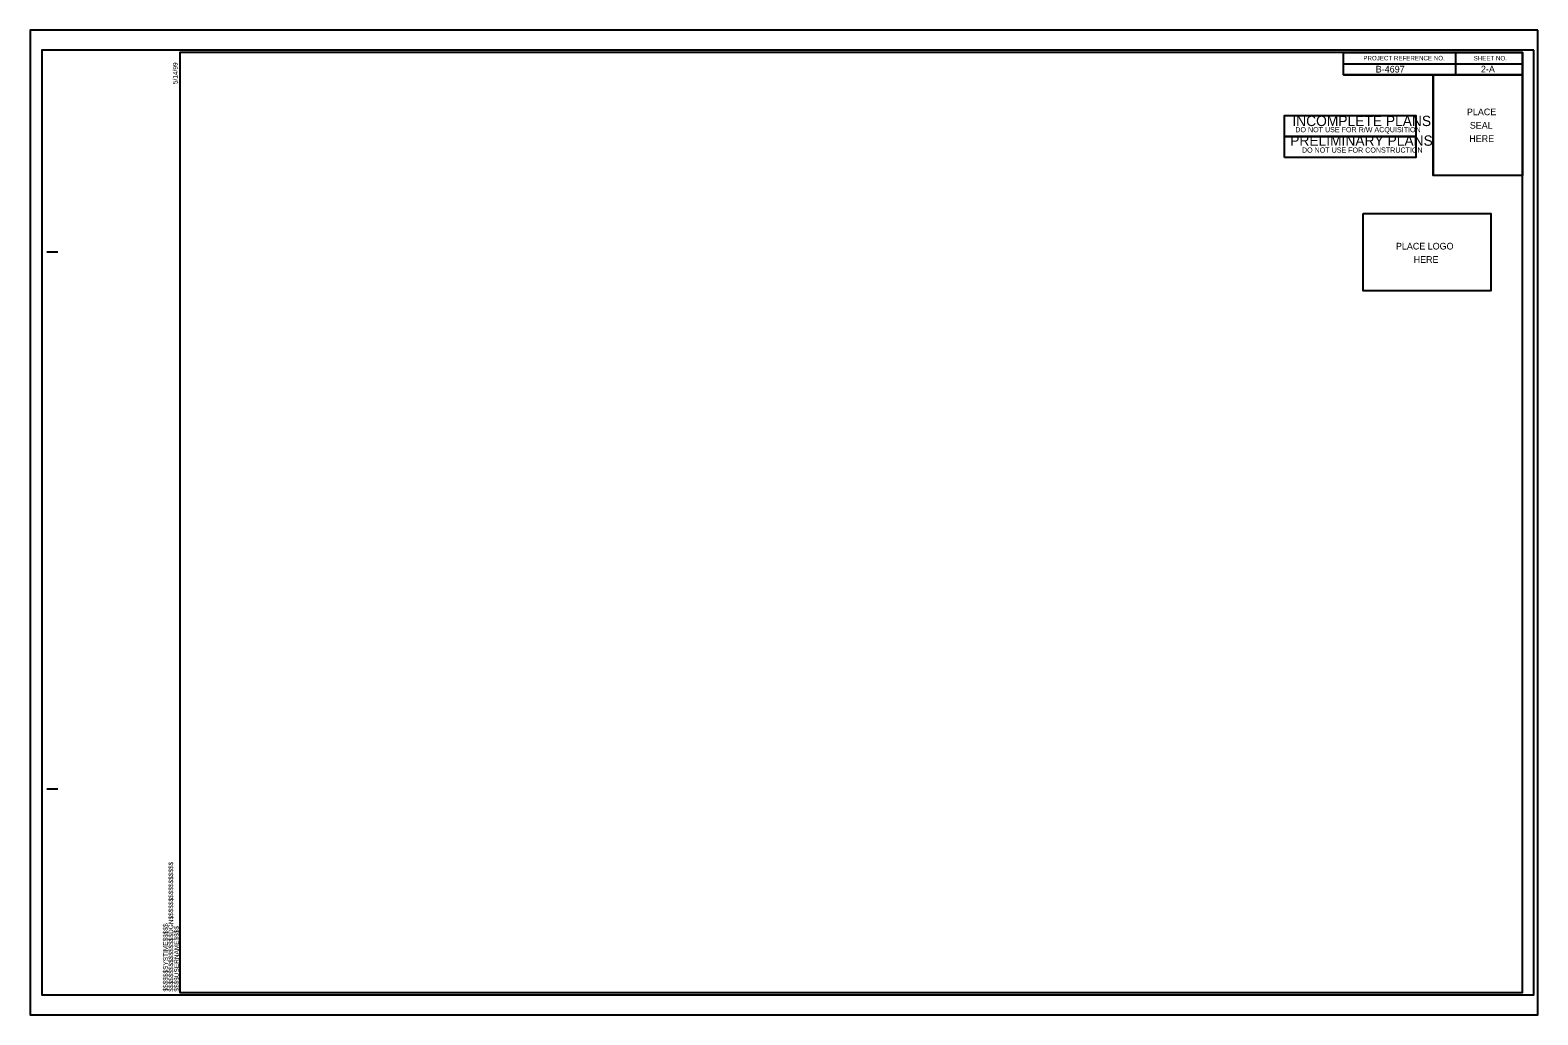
# Model space of a CAD drawing. Extents: x 573833 to 576101, y -53953 to -52800.
# Drawn here: x 573832.6 to 574001, y -53329.2 to -53219.2 of the extents above; entities that cross this region are included whole.
import ezdxf

# ---------------------------------------------------------------- set-up
doc = ezdxf.new("R2010")
doc.units = 0
for name, color, linetype in [('Sheet Border Standard 30in CELL', 7, 'Continuous'), ('Sheet Cutting Line CELL', 7, 'Continuous'), ('Sheet Data Field CELL', 7, 'Continuous'), ('Sheet Plot Border Inside CELL', 7, 'Continuous'), ('Sheet Plot Border Outside CELL', 7, 'Continuous'), ('Sheet Sticker Incomplete CELL', 7, 'Continuous'), ('Sheet Sticker Preliminary CELL', 7, 'Continuous'), ('Typical Pavement Slope CELL', 7, 'Continuous')]:
    doc.layers.add(name, color=color, linetype=linetype)

msp = doc.modelspace()

# ---------------------------------------------------------------- linework, layer by layer
at = {"layer": 'Sheet Border Standard 30in CELL'}
for p, q in [((573849.39, -53221.67), (573849.39, -53221.67)), ((573991.79, -53221.67), (573991.79, -53224.17)), ((573979.28, -53222.92), (573999.29, -53222.92)), ((573979.28, -53224.17), (573999.29, -53224.17)), ((573979.28, -53224.17), (573999.29, -53224.17)), ((573989.29, -53224.18), (573989.29, -53235.42)), ((573834.44, -53243.92), (573835.69, -53243.92)), ((573834.44, -53303.92), (573835.69, -53303.92))]:
    msp.add_line(p, q, dxfattribs=at)
for points in [[(573999.29, -53221.67), (573849.29, -53221.67), (573849.29, -53326.67), (573999.29, -53326.67)], [(573979.28, -53221.67), (573999.29, -53221.67), (573999.29, -53224.17), (573979.28, -53224.17)], [(573989.29, -53224.17), (573999.29, -53224.17), (573999.29, -53235.42), (573989.29, -53235.42)]]:
    msp.add_lwpolyline(points, close=True, dxfattribs=at)
at = {"layer": 'Sheet Cutting Line CELL'}
for p, q in [((574000.99, -53219.17), (573832.59, -53219.17)), ((573832.59, -53219.17), (573832.59, -53329.17)), ((573832.59, -53329.17), (574000.99, -53329.17))]:
    msp.add_line(p, q, dxfattribs=at)
at = {"layer": 'Sheet Plot Border Inside CELL'}
msp.add_lwpolyline([(574000.54, -53221.41), (573833.89, -53221.41), (573833.89, -53326.92), (574000.54, -53326.92)], close=True, dxfattribs=at)
at = {"layer": 'Sheet Plot Border Outside CELL'}
msp.add_lwpolyline([(574000.99, -53219.17), (573832.59, -53219.17), (573832.59, -53329.17), (574000.99, -53329.17)], close=True, dxfattribs=at)
at = {"layer": 'Sheet Sticker Incomplete CELL'}
msp.add_lwpolyline([(573972.68, -53231.05), (573972.68, -53228.7), (573987.38, -53228.7), (573987.38, -53231.05)], close=True, dxfattribs=at)
at = {"layer": 'Sheet Sticker Preliminary CELL'}
msp.add_lwpolyline([(573972.68, -53233.4), (573972.68, -53231.05), (573987.38, -53231.05), (573987.38, -53233.4)], close=True, dxfattribs=at)
at = {"layer": 'Typical Pavement Slope CELL'}
msp.add_lwpolyline([(573981.48, -53239.65), (573995.72, -53239.65), (573995.72, -53248.29), (573981.48, -53248.29)], close=True, dxfattribs=at)

# ---------------------------------------------------------------- texts
at = {"layer": 'Sheet Border Standard 30in CELL'}
for s, p in [('PROJECT REFERENCE NO.', (573981.5, -53222.54)), ('SHEET NO.', (573993.82, -53222.55))]:
    msp.add_text(s, height=0.5, dxfattribs=at).set_placement(p)
for s, p in [('5/14/99', (573849.06, -53225.19)), ('$$$$$$$$$$$$$$$$DGN$$$$$$$$$$$$$$$$', (573848.57, -53326.58)), ('$$$$$$SYSTIME$$$$$', (573847.97, -53326.56)), ('$$$$USERNAME$$$$', (573849.2, -53326.57))]:
    msp.add_text(s, height=0.525, rotation=90, dxfattribs=at).set_placement(p)
at = {"layer": 'Sheet Data Field CELL'}
for s, p in [('B-4697   ', (573982.88, -53223.9)), ('2-A', (573994.63, -53223.89))]:
    msp.add_text(s, height=0.75, dxfattribs=at).set_placement(p)
at = {"layer": 'Sheet Sticker Incomplete CELL'}
for s, height, p in [('INCOMPLETE PLANS', 1.152, (573973.57, -53229.88)), ('DO NOT USE FOR R/W ACQUISITION', 0.576, (573973.9, -53230.57))]:
    msp.add_text(s, height=height, dxfattribs=at).set_placement(p)
at = {"layer": 'Sheet Sticker Preliminary CELL'}
for s, height, p in [('PRELIMINARY PLANS', 1.152, (573973.33, -53232.08)), ('DO NOT USE FOR CONSTRUCTION', 0.576, (573974.64, -53232.85))]:
    msp.add_text(s, height=height, dxfattribs=at).set_placement(p)
at = {"layer": 'Typical Pavement Slope CELL'}
for s, p in [('PLACE ', (573993.07, -53228.67)), ('SEAL ', (573993.39, -53230.17)), ('HERE', (573993.33, -53231.66)), ('PLACE LOGO', (573985.14, -53243.67)), ('HERE', (573987.12, -53245.16))]:
    msp.add_text(s, height=0.746, dxfattribs=at).set_placement(p)

doc.saveas('drawing.dxf')
